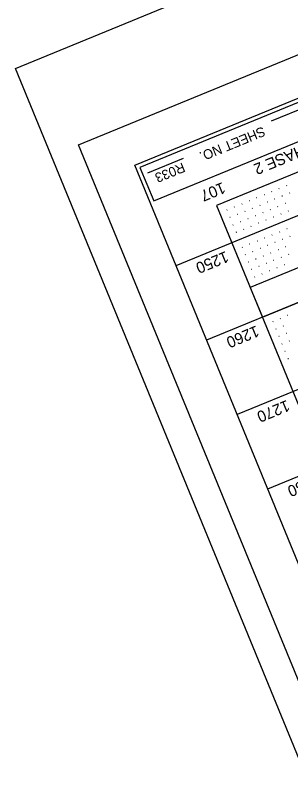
# Model space of a CAD drawing. Extents: x 2148770 to 2150891, y 142633 to 144465.
# Drawn here: x 2148769.7 to 2148940.4, y 143292.3 to 143776.3 of the extents above; entities that cross this region are included whole.
import ezdxf

# ---------------------------------------------------------------- set-up
doc = ezdxf.new("R2010")
doc.units = 0
for name, color, linetype in [('SHT_Plan_Profile_Sheet_Elev_Txt', 7, 'Continuous'), ('SHT_Plan_Profile_Sheet_Sta_Txt', 7, 'Continuous'), ('SHT_Plan_Profile_Sheet_Txt', 7, 'Continuous'), ('SHT_Plot_Shape_Full', 7, 'Continuous'), ('SHT_Plot_Shape_Half', 7, 'Continuous'), ('SHT_Profile_Grid_Major', 7, 'Continuous'), ('SHT_Profile_Grid_Minor', 7, 'Continuous'), ('SHT_Sheet_Border', 7, 'Continuous'), ('SHT_Standard_Sheet_Lines', 7, 'Continuous')]:
    doc.layers.add(name, color=color, linetype=linetype)

msp = doc.modelspace()

# ---------------------------------------------------------------- linework, layer by layer
at = {"layer": 'SHT_Plot_Shape_Full'}
msp.add_lwpolyline([(2150890.55, 143316.95), (2149225.42, 142633.31), (2148769.66, 143743.39), (2150434.78, 144427.04)], close=True, dxfattribs=at)
at = {"layer": 'SHT_Plot_Shape_Half'}
msp.add_lwpolyline([(2150799.14, 143324.02), (2149226.52, 142678.36), (2148808.74, 143695.93), (2150381.36, 144341.59)], close=True, dxfattribs=at)
at = {"layer": 'SHT_Profile_Grid_Major'}
for p, q in [((2150326.3, 144218.99), (2148869.31, 143620.81)), ((2150345.29, 144172.74), (2148888.3, 143574.55)), ((2150364.28, 144126.48), (2148907.29, 143528.3)), ((2150383.27, 144080.23), (2148926.28, 143482.05))]:
    msp.add_line(p, q, dxfattribs=at)
at = {"layer": 'SHT_Profile_Grid_Minor'}
for p, q in [((2148933.52, 143668.79), (2148933.29, 143668.69)), ((2148938.15, 143670.69), (2148937.92, 143670.59)), ((2148919.65, 143663.09), (2148919.42, 143663)), ((2148924.27, 143664.99), (2148924.04, 143664.9)), ((2148928.9, 143666.89), (2148928.67, 143666.8)), ((2148935.42, 143664.16), (2148935.19, 143664.07)), ((2148940.05, 143666.06), (2148939.82, 143665.97)), ((2148910.4, 143659.29), (2148910.17, 143659.2)), ((2148915.02, 143661.19), (2148914.79, 143661.1)), ((2148921.55, 143658.47), (2148921.32, 143658.37)), ((2148926.17, 143660.37), (2148925.94, 143660.27)), ((2148930.8, 143662.27), (2148930.57, 143662.17)), ((2148937.32, 143659.54), (2148937.09, 143659.44)), ((2148901.15, 143655.5), (2148900.92, 143655.4)), ((2148905.77, 143657.4), (2148905.54, 143657.3)), ((2148912.3, 143654.67), (2148912.07, 143654.57)), ((2148916.92, 143656.57), (2148916.69, 143656.47)), ((2148923.45, 143653.84), (2148923.22, 143653.75)), ((2148928.07, 143655.74), (2148927.84, 143655.65)), ((2148932.7, 143657.64), (2148932.47, 143657.54)), ((2148934.6, 143653.01), (2148934.37, 143652.92)), ((2148939.22, 143654.91), (2148938.99, 143654.82)), ((2148903.05, 143650.87), (2148902.82, 143650.78)), ((2148907.67, 143652.77), (2148907.44, 143652.68)), ((2148909.57, 143648.14), (2148909.34, 143648.05)), ((2148914.2, 143650.04), (2148913.96, 143649.95)), ((2148918.82, 143651.94), (2148918.59, 143651.85)), ((2148925.35, 143649.22), (2148925.11, 143649.12)), ((2148929.97, 143651.12), (2148929.74, 143651.02)), ((2148904.95, 143646.25), (2148904.71, 143646.15)), ((2148911.47, 143643.52), (2148911.24, 143643.42)), ((2148916.1, 143645.42), (2148915.86, 143645.32)), ((2148920.72, 143647.32), (2148920.49, 143647.22)), ((2148938.39, 143643.76), (2148938.16, 143643.67)), ((2148906.84, 143641.62), (2148906.61, 143641.53)), ((2148929.14, 143639.97), (2148928.91, 143639.87)), ((2148933.77, 143641.86), (2148933.54, 143641.77)), ((2148940.29, 143639.14), (2148940.06, 143639.04)), ((2148915.27, 143634.27), (2148915.04, 143634.17)), ((2148919.89, 143636.17), (2148919.66, 143636.07)), ((2148924.52, 143638.07), (2148924.29, 143637.97)), ((2148931.04, 143635.34), (2148930.81, 143635.25)), ((2148935.67, 143637.24), (2148935.44, 143637.14)), ((2148910.64, 143632.37), (2148910.41, 143632.27)), ((2148917.17, 143629.64), (2148916.94, 143629.55)), ((2148921.79, 143631.54), (2148921.56, 143631.45)), ((2148926.42, 143633.44), (2148926.19, 143633.35)), ((2148928.32, 143628.82), (2148928.09, 143628.72)), ((2148932.94, 143630.72), (2148932.71, 143630.62)), ((2148937.57, 143632.61), (2148937.34, 143632.52)), ((2148912.54, 143627.74), (2148912.31, 143627.65)), ((2148919.07, 143625.02), (2148918.83, 143624.92)), ((2148923.69, 143626.92), (2148923.46, 143626.82)), ((2148930.22, 143624.19), (2148929.98, 143624.1)), ((2148934.84, 143626.09), (2148934.61, 143625.99)), ((2148939.47, 143627.99), (2148939.23, 143627.89)), ((2148914.44, 143623.12), (2148914.21, 143623.02)), ((2148920.96, 143620.39), (2148920.73, 143620.3)), ((2148925.59, 143622.29), (2148925.36, 143622.2)), ((2148932.11, 143619.57), (2148931.88, 143619.47)), ((2148936.74, 143621.46), (2148936.51, 143621.37)), ((2148916.34, 143618.49), (2148916.11, 143618.4)), ((2148922.86, 143615.77), (2148922.63, 143615.67)), ((2148927.49, 143617.67), (2148927.26, 143617.57)), ((2148918.24, 143613.87), (2148918.01, 143613.77)), ((2148938.88, 143589.91), (2148938.65, 143589.82)), ((2148929.63, 143586.12), (2148929.4, 143586.02)), ((2148934.26, 143588.02), (2148934.03, 143587.92)), ((2148931.53, 143581.49), (2148931.3, 143581.4)), ((2148936.16, 143583.39), (2148935.93, 143583.3)), ((2148933.43, 143576.87), (2148933.2, 143576.77)), ((2148938.06, 143578.76), (2148937.82, 143578.67)), ((2148935.33, 143572.24), (2148935.1, 143572.15)), ((2148939.95, 143574.14), (2148939.72, 143574.04)), ((2148937.23, 143567.62), (2148937, 143567.52)), ((2148939.13, 143562.99), (2148938.9, 143562.89))]:
    msp.add_line(p, q, dxfattribs=at)
at = {"layer": 'SHT_Sheet_Border'}
msp.add_line((2148894.51, 143658.18), (2149074.91, 143218.77), dxfattribs=at)
for points in [[(2150699.45, 143310.11), (2149242.47, 142711.93), (2148843.68, 143683.25), (2150300.66, 144281.43)], [(2149079.81, 143753.17), (2149071.27, 143773.99), (2148846.94, 143681.89), (2148855.48, 143661.07)], [(2149061.75, 143645.77), (2149054.16, 143664.27), (2148915.4, 143607.3), (2148922.99, 143588.8)]]:
    msp.add_lwpolyline(points, close=True, dxfattribs=at)
msp.add_lwpolyline([(2149093.15, 143766.76), (2149102.65, 143743.63), (2148894.51, 143658.18)], dxfattribs=at)
at = {"layer": 'SHT_Standard_Sheet_Lines'}
for p, q in [((2148995.78, 143738.2), (2148928.52, 143710.58)), ((2148873.87, 143687.54), (2148851.55, 143678.38))]:
    msp.add_line(p, q, dxfattribs=at)

# ---------------------------------------------------------------- texts
at = {"layer": 'SHT_Plan_Profile_Sheet_Elev_Txt'}
for s, p in [('1250', (2148900.21, 143630.08)), ('1260', (2148919.2, 143583.83)), ('1270', (2148938.19, 143537.57)), ('1280', (2148957.18, 143491.32))]:
    msp.add_text(s, height=7, rotation=202.3213, dxfattribs=at).set_placement(p)
at = {"layer": 'SHT_Plan_Profile_Sheet_Sta_Txt'}
msp.add_text('107', height=7, rotation=202.3213, dxfattribs=at).set_placement((2148898.22, 143672.94))
at = {"layer": 'SHT_Plan_Profile_Sheet_Txt'}
for s, height, p in [('SHEET NO.', 6, (2148923.23, 143707.47)), ('PHASE 2', 7, (2148953.54, 143698.6)), ('R033', 6, (2148873.4, 143685.1))]:
    msp.add_text(s, height=height, rotation=202.3213, dxfattribs=at).set_placement(p)

doc.saveas('drawing.dxf')
